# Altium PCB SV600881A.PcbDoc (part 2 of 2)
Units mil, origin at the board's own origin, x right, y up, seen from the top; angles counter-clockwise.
Board outline 3700 x 3510 mil, 4 copper layers (Top Layer, MidLayer1, MidLayer2, Bottom Layer), stack 62.2 mil thick; 110 components, 46 nets, 261 pads, 195 vias.
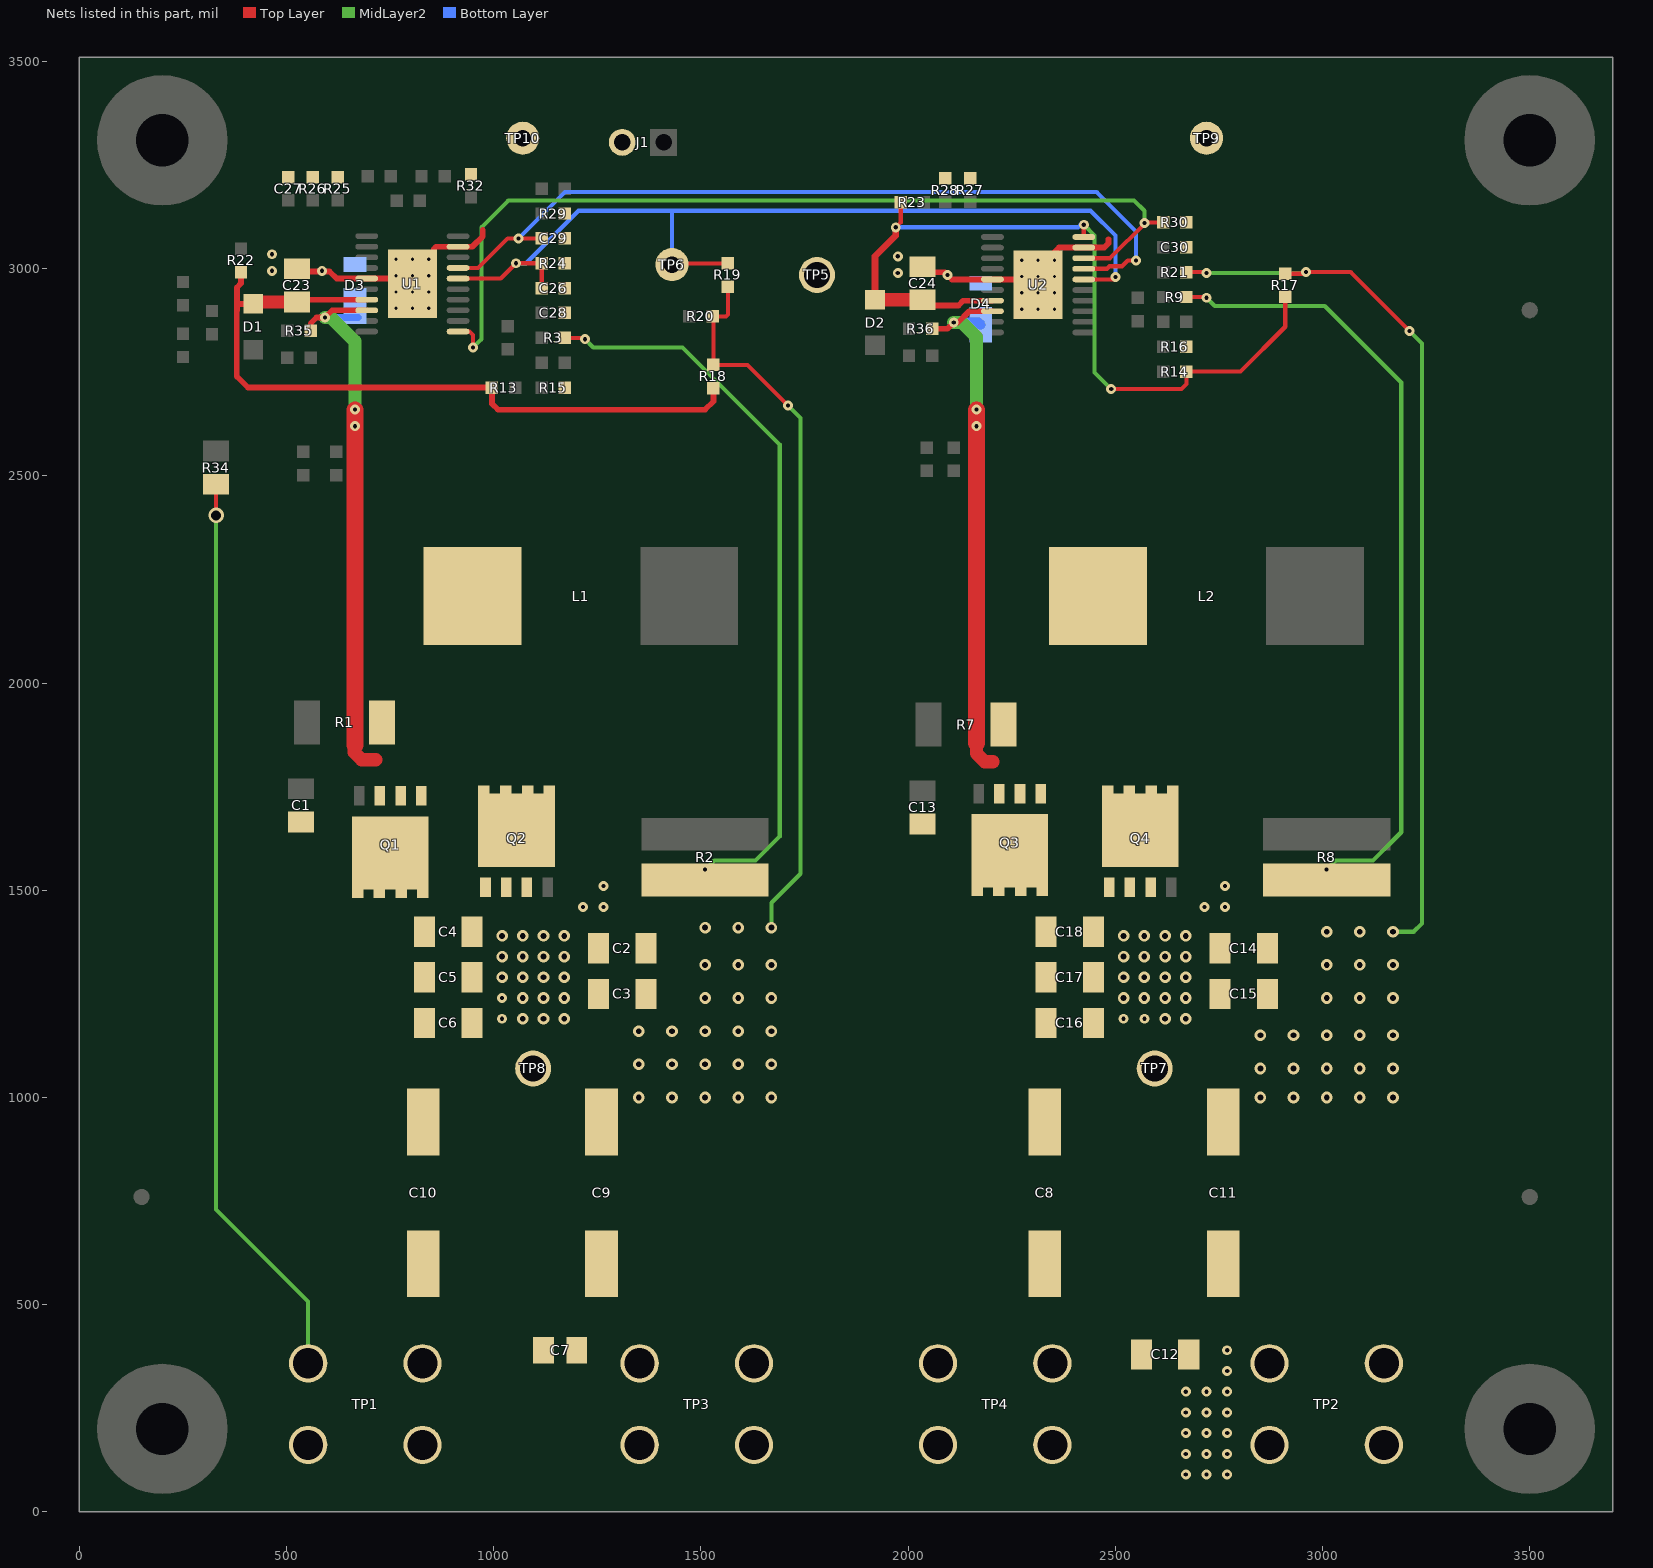
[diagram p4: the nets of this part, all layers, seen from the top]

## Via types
v1: diameter 24, hole 10, Top Layer to Bottom Layer, 84 vias
v2: diameter 28, hole 14, Top Layer to Bottom Layer, 84 vias
v3: diameter 19.68, hole 7.87, Top Layer to Bottom Layer, 24 vias
v4: diameter 38, hole 24, Top Layer to Bottom Layer, 2 vias
v5: diameter 26, hole 10, Top Layer to Bottom Layer, 1 vias

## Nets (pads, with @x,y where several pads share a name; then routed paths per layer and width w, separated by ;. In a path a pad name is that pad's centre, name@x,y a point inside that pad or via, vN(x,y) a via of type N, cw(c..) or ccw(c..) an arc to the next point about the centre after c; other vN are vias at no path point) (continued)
SGND: C2.2 C3.2 C4.2 C5.2 C6.2 C7.2 C8.2 C9.2 C10.2 C11.2 C12.2 C14.2 C15.2 C16.2 C17.2 C18.2 C23.1 C24.1 C26.2 C27.2 C28.2 C29.2 C30.2 D3.2 D4.2 J1.2 Q2.1 Q2.2 Q2.3 Q4.1 Q4.2 Q4.3 R15.1 R16.1 R24.1 R25.1 R26.1 R27.1 R28.1 R29.1 R30.1 R32.2 TP3.1 TP3.2 TP3.3 TP3.4 TP4.1 TP4.2 TP4.3 TP4.4 TP5.1 TP7.1 TP8.1 TP9.1 TP10.1 U1.9 U1.15 U1.21 U2.9 U2.15 U2.21 | length 894.8
  Top Layer w10: U1.21@800.81,2910.81 U1.21@813.6,2923.6
  Top Layer w12: U1.21@757.34,2976.4 v3(764.23,2983.29) ; v3(842.97,3022.66) 853.6,3033.29 U1.21@853.6,3043.6
  Top Layer w13.78: C23.1@543.6,2993.6 603.6,2993.6 620.81,2976.4 U1.15@693.37,2976.4 U1.21@757.34,2976.4 ; 855.6,3047.6 861.17,3053.17 U1.9@913.84,3053.17 948.17,3053.17 973.6,3078.6 973.6,3093.6 ; C24.1@2053.62,2991.5 2088.5,2991.5 v1(2095,2985) 2105.71,2974.29 U2.15@2203.39,2974.29 2267.36,2974.29 v3(2274.25,2981.18) ; U2.21@2313.62,2961.5 v3(2313.62,2981.18) 2313.62,3000.63 2364.06,3051.06 U2.9@2423.86,3051.06 2473.19,3051.06 2483.62,3061.5 2483.62,3071.5
  other v1: 1020,1190 2520,1190 2570,1190 1020,1240 1215,1460 1265,1460 2715,1460 2765,1460 1265,1510 2765,1510 1975,2990 465,2995 585,2995 1975,3030 465,3035
  other v2: 1070,1190 1120,1190 1170,1190 2620,1190 2670,1190 1070,1240 1120,1240 1170,1240 2520,1240 2570,1240 2620,1240 2670,1240 1020,1290 1070,1290 1120,1290 1170,1290 2520,1290 2570,1290 2620,1290 2670,1290 1020,1340 1070,1340 1120,1340 1170,1340 2520,1340 2570,1340 2620,1340 2670,1340 1020,1390 1070,1390 1120,1390 1170,1390 2520,1390 2570,1390 2620,1390 2670,1390
  other v3: 2274.25,2902.44 2313.62,2902.44 2352.99,2902.44 764.23,2904.55 803.6,2904.55 842.97,2904.55 2274.25,2941.81 2313.62,2941.81 2352.99,2941.81 764.23,2943.92 803.6,2943.92 842.97,2943.92 2352.99,2981.18 803.6,2983.29 842.97,2983.29 2274.25,3020.55 2313.62,3020.55 2352.99,3020.55 764.23,3022.66 803.6,3022.66
SS: C29.1 U1.7 U2.7 | length 2011.4
  Top Layer w10: U1.7@913.84,3001.99 962.3,3001.99 1033.6,3073.29 v1(1060,3073.29) C29.1@1115.6,3073.29 ; U2.7@2423.86,2999.88 2469.88,2999.88 2470,3000 2480,3000 2486,3006 2516,3006 2530,3020 v1(2550,3020)
  Bottom Layer w10: v1(1060,3073.29) 1171.71,3185 2455,3185 2550,3090 v1(2550,3020)
SW1: D3.1 L1.2 Q1.1 Q1.2 Q1.3 Q2.5 Q2.6 Q2.7 Q2.8 Q2.9 R1.1 R35.1 U1.18 | length 1435.3
  Top Layer w13.75: R35.1@558,2850 558,2868 572.2,2882.2 v1(592.52,2882.2) 609.94,2899.63 U1.18@693.37,2899.63
  Top Layer w32: 665,1850 662.96,1847.96 662.96,1832.96 680.91,1815 715,1815
  Top Layer w40: 665,1850 v1(665,2620) v1(665,2660)
  MidLayer2 w32: v1(592.52,2882.2) 607.8,2882.2 665,2825 v1(665,2660) v1(665,2620)
  Bottom Layer w16: v1(592.52,2882.2) D3.1@672.8,2882.2
SW2: D4.1 L2.2 Q3.1 Q3.2 Q3.3 Q4.5 Q4.6 Q4.7 Q4.8 Q4.9 R7.1 R36.1 U2.18 | length 1392.9
  Top Layer w13: v1(2110,2870) v1@2120,2870
  Top Layer w13.75: R36.1@2058,2855 2095,2855 v1(2110,2870) ; v1@2120,2870 2147.52,2897.52 U2.18@2203.39,2897.52
  Top Layer w32: 2165,1855 2165,1830 2185,1810 2205,1810
  Top Layer w40: 2165,1855 v1(2165,2620) v1(2165,2660)
  MidLayer2 w32: v1(2110,2870) 2130,2870 2165,2835 v1(2165,2660) v1(2165,2620)
  Bottom Layer w24: v1(2110,2870) 2169.8,2870 D4.1@2175,2864.8
SYNC: R30.2 U1.1 U2.8 | length 2262.7
  Top Layer w10: U1.1@913.84,2848.44 941.56,2848.44 950,2840 v1(950,2810) ; U2.8@2423.86,3025.47 2487.28,3025.47 2573.62,3111.81 R30.2@2615.62,3111.81
  MidLayer2 w10: v1(950,2810) 970,2830 970,3100 1035,3165 2545,3165 2570,3140 v1(2570,3110)
UVLO: C26.1 R19.1 R24.2 TP6.1 U1.6 U2.6 | length 2250.2
  Top Layer w10: U1.6@913.84,2976.4 1016.71,2976.4 v1(1053.6,3013.29) R24.2@1115.6,3013.29 C26.1@1115.6,2953.29 ; TP6.1@1430,3010 1433,3013 R19.1@1565,3013 ; U2.6@2423.86,2974.29 2494.29,2974.29 v1(2500,2980)
  Bottom Layer w10: v1@1056.89,3010 v1(1053.6,3013.29) 1078.11,3013.29 1204.83,3140 1430,3140 ; TP6.1@1430,3010 1430,3140 ; v1(2500,2980) 2500,3080 2440,3140 1430,3140
V+: C2.1 C3.1 C12.1 C14.1 C15.1 R2.1 R3.2 R8.1 R9.2 R17.2 R18.1 R19.2 R20.2 R21.2 TP2.1 TP2.2 TP2.3 TP2.4 | length 7611.7
  Top Layer w10: R3.2@1171.6,2833.29 1216.71,2833.29 v1(1220,2830) ; R20.2@1528,2890 R20.2@1530,2888 ; R19.2@1565,2957 1565,2890 1560,2885 1533,2885 R20.2@1530,2888 ; v1(1710,2670) 1612,2768 R18.1@1530,2768 R20.2@1530,2888 ; R9.2@2671.62,2931.81 2718.19,2931.81 v1(2720,2930) ; R21.2@2671.62,2991.81 2718.19,2991.81 v1(2720,2990) ; R17.2@2910,2988 2956,2988 v1(2960,2992) 3068,2992 v1(3210,2850)
  MidLayer2 w10: v1(1220,2830) 1240,2810 1455.46,2810 1690,2575.46 1690,1630 1632,1572 1532,1572 v1(1510,1550) ; v2(1670,1410) 1670,1470 1740,1540 1740,2640 v1(1710,2670) ; v1(2720,2930) 2740,2910 3005.46,2910 3190,2725.46 3190,1640 3122,1572 3032,1572 v1(3010,1550) ; v1(2720,2990) 2958,2990 v1(2960,2992) ; v2(3170,1400) 3220,1400 3240,1420 3240,2820 v1(3210,2850)
  other v1: 2670,90 2720,90 2770,90 2670,140 2720,140 2770,140 2670,190 2720,190 2770,190 2670,240 2720,240 2770,240 2670,290 2720,290 2770,290 2770,340 2770,390
  other v2: 1350,1000 1430,1000 1510,1000 1590,1000 1670,1000 2850,1000 2930,1000 3010,1000 3090,1000 3170,1000 2850,1070 2930,1070 3010,1070 3090,1070 3170,1070 1350,1080 1430,1080 1510,1080 1590,1080 1670,1080 2850,1150 2930,1150 3010,1150 3090,1150 3170,1150 1350,1160 1430,1160 1510,1160 1590,1160 1670,1160 1510,1240 1590,1240 1670,1240 3010,1240 3090,1240 3170,1240 1510,1320 1590,1320 1670,1320 3010,1320 3090,1320 3170,1320 3010,1400 3090,1400 1510,1410 1590,1410
VCC: C23.2 D1.2 R13.2 R18.2 R22.2 U1.17 | length 1824.1
  Top Layer w13.78: 380,2900 380,2740 406.71,2713.29 R13.2@995.6,2713.29 995.6,2674.4 1010,2660 1510,2660 1530,2680 R18.2@1530,2712 ; 380,2915.12 D1.2@420,2915.12 D1.2@425,2915.12 ; C23.2@525,2930 548.32,2930 C23.2@543.6,2925.29 ; C23.2@553.6,2925.22 U1.17@693.37,2925.22
  Top Layer w14: 380,2900 380,2915.12 380,2955 390,2965 R22.2@390,2992
  Top Layer w16: D1.2@425,2915.12 D1.2@429.88,2920
  Top Layer w32: D1.2@429.88,2920 C23.2@525,2920 C23.2@530,2920
VCC2: C24.2 D2.2 R14.2 R17.1 R23.2 U2.10 U2.17 | length 2044.4
  Top Layer w10: v1(1970,3100) 1982,3112 R23.2@1982,3160 ; v1@2420,3110 v1(2423.86,3106.14) U2.10@2423.86,3076.65 ; v1(2490,2710) 2660,2710 2671.62,2721.62 R14.2@2671.62,2751.81 2801.81,2751.81 2910,2860 R17.1@2910,2932
  Top Layer w13.78: C24.2@2045,2925 2058.5,2911.5 2121.5,2911.5 2133.11,2923.11 U2.17@2203.39,2923.11
  Top Layer w16: D2.2@1920,2915.12 D2.2@1920,2925.12 1920,3030 1970,3080 v1(1970,3100)
  Top Layer w32: D2.2@1929.88,2925 C24.2@2035,2925 C24.2@2045,2925
  MidLayer2 w10: v1@2420,3110 v1(2423.86,3106.14) 2450,3080 2450,2750 v1(2490,2710)
  Bottom Layer w10: v1(1970,3100) 2410,3100 v1@2420,3110
VOUT: C1.1 C4.1 C5.1 C6.1 C7.1 C8.1 C9.1 C10.1 C11.1 C13.1 C16.1 C17.1 C18.1 Q1.5 Q1.6 Q1.7 Q1.8 Q1.9 Q3.5 Q3.6 Q3.7 Q3.8 Q3.9 R34.1 TP1.1 TP1.2 TP1.3 TP1.4 | length 2213.5
  Top Layer w10: v4(330,2405) R34.1@330,2480
  MidLayer2 w10: v4(330,2405) 330,730 552,508 TP1.3@552,358.5
pads on no net: FID1.1 FID2.1 FID3.1 H3.1 H4.1 H7.1 H8.1 U2.1

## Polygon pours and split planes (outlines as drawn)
SGND on Top Layer "Top Layer-No Net 17" (solid, pour order 35): 745,3120 750,3125 855,3125 860,3120 860,2825 885,2800 910,2800 915,2795 915,2735 910,2730 705,2730 700,2735 700,2795 705,2800 720,2800 745,2825
V+ on Top Layer "Top Layer-No Net 2" (solid, pour order 53): 2820,450 3220,450 3220,1550 3210,1560 2830,1560 2820,1550
V+ on Top Layer "Top Layer-No Net 2" (solid, pour order 43): 1320,970 1330,960 1710,960 1720,970 1720,1550 1710,1560 1330,1560 1320,1550
NetL1_1 on Top Layer "Top Layer-No Net 3" (solid, pour order 46): 1720,1610 1710,1600 1330,1600 1320,1610 1320,2320 1340,2340 1700,2340 1720,2320
SW1 on Top Layer "Top Layer-No Net 4" (solid, pour order 49): 1280,1570 1270,1560 910,1560 900,1570 900,1690 890,1700 700,1700 700,2320 720,2340 1070,2340 1090,2320 1090,2010 1280,1820
SW2 on Top Layer "Top Layer-No Net 4" (solid, pour order 50): 2780,1570 2770,1560 2410,1560 2400,1570 2400,1690 2390,1700 2200,1700 2200,2320 2220,2340 2570,2340 2590,2320 2590,2010 2780,1820
NetL2_1 on Top Layer "Top Layer-No Net 3" (solid, pour order 47): 3220,1610 3210,1600 2830,1600 2820,1610 2820,2330 2840,2350 3200,2350 3220,2330
SGND on Top Layer "Top Layer-No Net 1" (solid, pour order 48): 2290,850 2300,840 2790,840 2800,850 2800,1520 2790,1530 2410,1530 2400,1520 2400,1100 2380,1080 2320,1080 2290,1050
VOUT on Top Layer "Top Layer-No Net 5" (solid, pour order 51): 2280,960 2280,1060 2310,1090 2380,1090 2380,1660 2360,1680 1790,1680 1770,1650 1770,960
VOUT on Top Layer "Top Layer-No Net 6" (solid, pour order 56): 400,50 380,70 380,305 330,380 330,950 350,970 880,970 880,940 1750,940 1770,960 2280,960 2280,840 2300,820 2790,820 2810,800 2810,490 2790,470 1160,470 1140,450 1140,70 1120,50
SGND on Top Layer "Top Layer-No Net" (solid, pour order 42): 1155,2690 1155,3155 1065,3155 983.6,3073.29 980,3070 960,3070 960,3190 950,3200 920,3200 910,3210 910,3250 900,3260 650,3260 640,3250 640,3220 630,3210 480,3210 470,3220 470,3340 480,3350 1350,3350 1370,3330 1370,2710 1350,2690
VOUT on Top Layer "Top Layer-No Net 5" (solid, pour order 52): 880,960 880,1670 870,1680 340,1680 330,1670 330,960
V+ on Top Layer "Top Layer-No Net 11" (solid, pour order 41): 2660,450 3220,450 3220,60 3210,50 2660,50 2650,60 2650,440
SGND on Top Layer "Top Layer-No Net 10" (solid, pour order 54): 1200,50 1180,70 1180,430 1200,450 2570,450 2590,430 2590,70 2570,50 1890,50 1880,60 1880,410 1870,420 1830,420 1820,410 1820,60 1810,50
SGND on Top Layer "Top Layer-No Net 1" (solid, pour order 45): 800,847.76 1290,847.76 1300,860 1300,1520 1290,1530 910,1530 900,1520 900,1115 815,1115 790,1090 790,860
SGND on Top Layer "Top Layer-No Net 9" (solid, pour order 34): 2125,2970 1955,2970 1955,3040 1965,3055 2085,3055 2100,3040 2100,3015 2125,2990
SGND on Top Layer "Top Layer-No Net 7" (solid, pour order 33): 450,3055 450,2975 610,2975 610,2995 550,3055
SGND on Top Layer "Top Layer-No Net 17" (solid, pour order 37): 2255,3130 2245,3140 2230,3140 2220,3150 2220,3190 2230,3200 2410,3200 2420,3190 2420,3150 2410,3140 2380,3140 2370,3130 2370,2825 2395,2800 2410,2800 2420,2790 2420,2730 2410,2720 2220,2720 2210,2730 2210,2790 2220,2800 2230,2800 2255,2825
SGND on Top Layer "Top Layer-No Net 8" (solid, pour order 40): 2655,2780 2655,3150 2580,3150 2485,3055 2450,3055 2470,3075 2470,3165 2425,3210 2070,3210 2070,3340 2080,3350 2850,3350 2870,3330 2870,2780
V+ on MidLayer2 "MidLayer2-No Net" (solid, pour order 59): 2660,50 3290,50 3310,70 3310,310 3450,450 3450,1430 3430,1450 2840,1450 2820,1430 2820,1160 2800,1140 1740,1140 1720,1160 1720,1430 1700,1450 1340,1450 1320,1430 1320,550 1340,530 2620,530 2640,510 2640,70
SGND on MidLayer2 "MidLayer1-No Net" (solid, pour order 60): 3650,50 1890,50 1880,60 1880,410 1870,420 1830,420 1820,410 1820,60 1810,50 50,50 49.29,3459.92 3649.29,3459.92
SW1 on Bottom Layer "Bottom Layer-No Net" (solid, pour order 61): 690,2870 585,2870 580,2875 580,2890 585,2895 690,2895
SW2 on Bottom Layer "Bottom Layer-No Net 1" (solid, pour order 62): 2195,2855 2100,2855 2095,2860 2095,2880 2100,2885 2195,2885
SGND on Bottom Layer "MidLayer1-No Net" (solid, pour order 63): 3650,50 1890,50 1880,60 1880,410 1870,420 1830,420 1820,410 1820,60 1810,50 50,50 50,3460 3650,3460
SGND on MidLayer1 "MidLayer1-No Net" (solid, pour order 57): 3650,50 1890,50 1880,60 1880,410 1870,420 1830,420 1820,410 1820,60 1810,50 50,50 50,3460 3650,3460

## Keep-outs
Keep-Out Layer:
  lines w10: -5,-5 3705,-5 3705,3515 -5,3515 -5,-5
  text ".Layer_Name" at -78,-863.49 h60

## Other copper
Top Layer:
  rectangle net NetC1_2: 485,1720 585,1980
  rectangle net NetC13_2: 1990,1715 2080,1975
  pour cut-out: 725,2832.5 725,3097.5 735,3097.5 735,2832.5
  pour cut-out: 870,2827.5 870,3092.5 880,3092.5 880,2827.5
  pour cut-out: 2239.25,2827.47 2239.25,3092.47 2249.25,3092.47 2249.25,2827.47
  pour cut-out: 2380,2827.5 2380,3092.5 2390,3092.5 2390,2827.5
  pour cut-out: 2820,1587.76 3224.68,1587.76 3224.68,1572.24 2820,1572.24
  pour cut-out: 1320,1587.76 1724.68,1587.76 1724.68,1572.24 1320,1572.24
  text ".Layer_Name" at -78,-863.49 h60
MidLayer1:
  pour cut-out: 1270,3290 1280,3275 1300,3265 1320,3265 1340,3275 1350,3290 1350,3320 1340,3335 1320,3345 1300,3345 1280,3335 1270,3320
  pour cut-out: 1030,3300 1040,3285 1060,3275 1080,3275 1100,3285 1110,3300 1110,3330 1100,3345 1080,3355 1060,3355 1040,3345 1030,3330
  pour cut-out: 2680,3300 2690,3285 2710,3275 2730,3275 2750,3285 2760,3300 2760,3330 2750,3345 2730,3355 2710,3355 2690,3345 2680,3330
  pour cut-out: 2680,3300 2690,3285 2710,3275 2730,3275 2750,3285 2760,3300 2760,3330 2750,3345 2730,3355 2710,3355 2690,3345 2680,3330
  text ".Layer_Name" at -80,-865 h60
MidLayer2:
  pour cut-out: 2680,3300 2690,3285 2710,3275 2730,3275 2750,3285 2760,3300 2760,3330 2750,3345 2730,3355 2710,3355 2690,3345 2680,3330
  pour cut-out: 1030,3300 1040,3285 1060,3275 1080,3275 1100,3285 1110,3300 1110,3330 1100,3345 1080,3355 1060,3355 1040,3345 1030,3330
  pour cut-out: 1270,3290 1280,3275 1300,3265 1333.33,3265 1350,3290 1350,3320 1340,3335 1320,3345 1300,3345 1280,3335 1270,3320
  text ".Layer_Name" at -80,-865 h60
Bottom Layer:
  pour cut-out: 1270,3290 1280,3275 1300,3265 1320,3265 1340,3275 1350,3290 1350,3320 1340,3335 1320,3345 1300,3345 1280,3335 1270,3320
  pour cut-out: 1090,3265 1050,3265 1020,3295 1020,3335 1050,3365 1090,3365 1120,3335 1120,3295
  pour cut-out: 2745,3265 2700,3265 2670,3295 2670,3340 2695,3365 2740,3365 2770,3335 2770,3295
  text ".Layer_Name" at -78,-863.49 h60

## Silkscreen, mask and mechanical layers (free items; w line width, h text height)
Top Overlay:
  lines w7: 655,2785 655,2795 625,2825 ; 2170,2780 2160,2790 2125,2790 2110,2805 ; 625,2825 625,2810 640,2825 625,2825 ; 2110,2805 2110,2790 2125,2805 2110,2805
  text "EXT" at 1250,3375 h44
  text "SYNC" at 1420,3375 h44
  text "LM5122EVM-2PH" at 175,1380 h78.74 r90
  text "HOT SURFACE" at 3555,875 h78.74 r90
  text "HOT SURFACE" at 2060,735 h78.74 r90
  text "28VDC" at 130,610 h70
  text "9-20VDC" at 3060,600 h70
  text "7A" at 205,500 h70
  text "GND" at 1445,495 h60
  text "GND" at 1985,495 h60
  text "30A MAX" at 3170,490 h60
  text "VOUT" at 450,475 h60
  text "VIN" at 2905,465 h60
  text "MAX" at 185,410 h60
  text ".Layer_Name" at -78,-863.49 h60
Bottom Overlay:
  region: 85,2370 85,2070 185,2070 185,2370
  text "-" at 84.5,2005 h60 r270
  text "A" at 105,1970 h60 r270
  text ".PRJ_Number" at 105,1435 h60 r270
  text ".Layer_Name" at -78,-863.49 h60
Top Paste:
  text ".Layer_Name" at -78,-863.49 h60
Bottom Paste:
  text ".Layer_Name" at -78,-863.49 h60
Top Solder:
  circle w45: c1235,1625 r20
  circle w45: c2735,1635 r20
  text ".Layer_Name" at -78,-863.49 h60
  text ".Layer_Name" at -78,-863.49 h60
Bottom Solder:
  text ".Layer_Name" at -78,-863.49 h60
Drill Guide:
  text ".Layer_Name" at -78,-863.49 h60
M1 Board Outline:
  the board outline again, w10
  text ".Layer_Name" at -78,-863.49 h60
M2 Board Dimensions:
  rectangle: -655.5,-290.5 -530.5,-165.5
  rectangle: -530.5,-415.5 -155.5,-290.5
  lines w7: -655.5,-290.5 344.5,-290.5 ; -530.5,-415.5 -530.5,-165.5 ; -405.5,-415.5 -405.5,-165.5 ; -155.5,-415.5 -155.5,-165.5 ; 94.5,-415.5 94.5,-165.5 ; -655.5,-415.5 344.5,-415.5 344.5,-165.5 -655.5,-165.5 -655.5,-415.5
  lines w10: -655.5,-480.5 -655.5,-460.5 ; -595.5,-490.5 -655.5,-470.5 ; -595.5,-450.5 -655.5,-470.5 ; -431.42,-470.5 -655.5,-470.5 ; 120.42,-470.5 344.5,-470.5 ; 284.5,-490.5 344.5,-470.5 ; 284.5,-450.5 344.5,-470.5 ; 344.5,-480.5 344.5,-460.5
  text "1000 (mil)" at -421.42,-506.49 h60
  text ".Layer_Name" at -78,-863.49 h60
M3 3D STEP Top:
  text ".Layer_Name" at -78,-863.49 h60
M4 3D STEP Bottom:
  text ".Layer_Name" at -78,-863.49 h60
M5 Assembly Top:
  lines w7: 4524,55.5 5649,55.5 ; 4524,178 5646.5,178 ; 4839,-64.5 4839,298 ; 5224,-64.5 4524,-64.5 ; 5224,298 4524,298 ; 4524,-64.5 5649,-64.5 5649,298 4524,298 ; 4524,-64.5 4524,298
  lines w10: -947,-930.17 5653,-930.17 ; -947,-726.83 5655,-726.83 ; -947,-523.5 -947,-1133.5 3058,-1133.5 5655,-1133.5 5655,-523.5 -946.5,-523.5 -946.5,-1133.5 629,-1133.5 ; 1518,-1133.5 1518,-523.5 ; 2785,-726.83 2785,-523.5 ; 3625,-726.83 3625,-523.5 ; 4247,-1140 4247,-937.17
  text "TABLE 1" at 4911.5,333 h40
  text "Variant" at 4549,223 h40
  text "Label text" at 4984,223 h40
  text "001" at 4616.5,103 h40
  text "LM5122EVM-2PH" at 4894,100.5 h40
  text "002" at 4616.5,-22 h40
  text "N/A" at 4889,-24.5 h40
  text "COMPONENTS MARKED 'DNP' SHOULD NOT BE POPULATED, AND MAY NOT BE IN BILL OF MATERIALS" at 498.5,-318.5 h60
  text "ASSEMBLY VARIANT:" at 498,-434 h60
  text ".VariantName" at 1534,-434 h60
  text "PCB VIEWED FROM TOP SIDE" at -883.5,-655.67 h60
  text "BOARD #:" at 1593,-655.67 h60
  text ".PRJ_Number" at 2138.5,-655.67 h60
  text "REV:" at 2983,-655.67 h60
  text ".PCB_Rev" at 3274.5,-655.67 h60
  text "SVN REV:" at 3821,-655.67 h60
  text ".VersionControl_RevNumber" at 4327,-655.67 h60
  text "IGNORE ->" at -883.5,-858.49 h60
  text ".Layer_Name" at -80,-860 h60
  text "PLOT NAME =" at -883.5,-1064.34 h60
  text ".plot_File_Name" at -78,-1064.34 h60
  text "GENERATED    :" at 1595,-1064.34 h60
  text ".Print_Date" at 2464.5,-1064.34 h60
  text ".Print_Time" at 3193.5,-1064.34 h60
  text "TEXAS INSTRUMENTS" at 4458,-1064.34 h60
M6 Assembly Bottom:
  lines w10: -947.5,-727.33 5654.5,-727.33 ; -945.5,-930.67 5654.5,-930.67 ; 460.5,-1140.5 460.5,-937.67 ; 1082.5,-727.33 1082.5,-524 ; 1922.5,-727.33 1922.5,-524 ; 3189.5,-1134 3189.5,-524 ; 4078.5,-1134 5654,-1134 5654,-524 -947.5,-524 -947.5,-1134 1649.5,-1134 5654.5,-1134 5654.5,-524
  text "COMPONENTS MARKED 'DNP' SHOULD NOT BE POPULATED, AND MAY NOT BE IN BILL OF MATERIALS" at 5447,-318 h60
  text ".VariantName" at 4403,-434 h60
  text "ASSEMBLY VARIANT:" at 5442,-434 h60
  text ".VersionControl_RevNumber" at 380.5,-656.17 h60
  text "SVN REV:" at 886.5,-656.17 h60
  text ".PCB_Rev" at 1433,-656.17 h60
  text "REV:" at 1724.5,-656.17 h60
  text ".PRJ_Number" at 2569,-656.17 h60
  text "BOARD #:" at 3114.5,-656.17 h60
  text "PCB VIEWED FROM BOTTOM SIDE" at 5591,-656.17 h60
  text "IGNORE ->" at 1892.85,-858.49 h60
  text ".Layer_Name" at -80,-860 h60
  text "TEXAS INSTRUMENTS" at 249.5,-1064.84 h60
  text ".Print_Time" at 1514,-1064.84 h60
  text ".Print_Date" at 2243,-1064.84 h60
  text "GENERATED    :" at 3112.5,-1064.84 h60
  text ".plot_File_Name" at 4785.5,-1064.84 h60
  text "PLOT NAME =" at 5591,-1064.84 h60
M9 Title Sheet:
  lines w10: -1146.5,1041.5 -946.5,1041.5 ; -1146.5,3416.5 -946.5,3416.5 ; -1146.5,5791.5 -946.5,5791.5 ; 1353.5,-1333.5 1353.5,-1133.5 ; 1353.5,7966.5 1353.5,8166.5 ; 3853.5,-1333.5 3853.5,-1133.5 ; 3853.5,7966.5 3853.5,8166.5 ; 5666,-1133.5 5666,-523.5 10648.5,-523.5 ; 6353.5,-1333.5 6353.5,-1133.5 ; 6353.5,7966.5 6353.5,8166.5 ; 8853.5,-1333.5 8853.5,-1133.5 ; 8853.5,7966.5 8853.5,8166.5 ; 10648.5,-1133.5 10648.5,-523.5 ; 10648.5,-823.5 13648.5,-823.5 ; 10648.5,-223.5 13648.5,-223.5 ; 10649.5,370.5 13649.5,370.5 ; 11353.5,-1333.5 11353.5,-1133.5 ; 11353.5,7966.5 11353.5,8166.5 ; 12153.5,-1123.5 12153.5,-523.5 ; 13648.5,-523.5 10648.5,-523.5 ; 13648.5,76.5 10648.5,76.5 ; 13653.5,66.5 13653.5,-1133.5 ; 13653.5,871 10649.5,871 10648.5,871 10648.5,370.5 10648.5,76.5 ; 13653.5,1041.5 13853.5,1041.5 ; 13653.5,3416.5 13853.5,3416.5 ; 13653.5,5791.5 13853.5,5791.5 ; 10648.5,-523.5 10648.5,76.5 ; 13653.5,-1133.5 13653.5,7966.5 -946.5,7966.5 -946.5,-1133.5 13653.5,-1133.5 ; -1146.5,-1333.5 -1146.5,8166.5 13853.5,8166.5 13853.5,-1333.5 -1146.5,-1333.5
  text "1" at 84.84,8036.5 h70
  text "2" at 2580.5,8036.5 h70
  text "3" at 5069.84,8036.5 h70
  text "4" at 7576.51,8036.5 h70
  text "5" at 10075.5,8036.5 h70
  text "6" at 12580.5,8036.5 h70
  text "A" at -1071.5,6893.5 h70
  text "A" at 13728.5,6893.5 h70
  text "B" at -1071.5,4513.5 h70
  text "B" at 13728.5,4513.5 h70
  text "C" at -1071.5,2138.5 h70
  text "C" at 13728.5,2138.5 h70
  text "PROJECT TITLE:" at 10688.5,277.5 h45
  text ".PRJ_Title" at 10738.5,144.17 h70
  text "DESIGNED FOR:" at 10688.5,-23.5 h45
  text ".PRJ_Customer" at 10738.5,-163.5 h70
  text "D" at -1071.5,-231.5 h70
  text "D" at 13728.5,-231.5 h70
  text "FILE NAME:" at 10688.5,-323.5 h45
  text ".PCB_File_Name_No_Path" at 10738.5,-443.5 h70
  text "ENGINEER:" at 10688.5,-613.5 h45
  text "LAYOUT BY:" at 12193.5,-613.5 h45
  text ".PRJ_Engineer" at 10738.5,-768.49 h70
  text ".PCB_Layout" at 12244,-768.49 h70
  text "ALTIUM DESIGNER VERSION:" at 12193.5,-923.5 h45
  text ".print_Scale" at 10738.5,-1056.83 h70
  text ".Application_BuildNumber" at 12244,-1056.83 h70
  text "1" at 84.84,-1263.5 h70
  text "2" at 2580.5,-1263.5 h70
  text "3" at 5069.84,-1263.5 h70
  text "4" at 7576.51,-1263.5 h70
  text "5" at 10075.5,-1263.5 h70
  text "6" at 12580.5,-1263.5 h70
M10 Fab Notes:
  drawing of 203 lines, arcs and shapes, not listed
  text "DESIGN INFORMATION" at 11721.02,6810 h60
  text "(REFER ALSO ARRAY/PANEL PROFILING INFORMATION)" at 11359.46,6648.29 h60
  text "BOARD SIZE" at 10673.46,6644 h60
  text "3700MIL" at 11135.78,6516.18 h60
  text "X" at 11641.46,6516.18 h60
  text "3150MIL" at 11872.78,6516.18 h60
  text "Number of Layers :" at 11076.46,6319 h60
  text "4" at 12171.27,6309 h60
  text "MIN. TRACK WIDTH:" at 11076.46,6180 h60
  text "8" at 12172.7,6180 h60
  text "MIL" at 12327.46,6180 h60
  text "MIN. CLEARANCE:" at 11076.46,6048 h60
  text "8" at 12172.7,6048 h60
  text "MIL" at 12327.46,6048 h60
  text "MIN. VIA PAD SIZE:" at 11076.46,5916 h60
  text "20" at 12142.71,5916 h60
  text "MIL" at 12327.46,5916 h60
  text "0.05mm (2MIL)" at 11771.46,5774.29 h60
  text "MINIMUM ANNULAR RING" at 10747.23,5770 h60
  text "EXTERNAL" at 12479.46,5770 h60
  text "PER" at 10947.23,5652 h60
  text "IPC-D-275 CLASS 2 LEVEL C" at 11167.23,5652 h60
  text "MIL, HOLES" at 12655.46,5539.71 h60
  text "+/-" at 12263,5539 h60
  text "+/-" at 13117,5539 h60
  text "REGISTRATION TOLERANCES:" at 10747.23,5534 h60
  text "METAL" at 11947,5534 h60
  text "5" at 12523.2,5534 h60
  text "3" at 13356.2,5534 h60
  text "MIL" at 13472.46,5534 h60
  text "MATERIAL:" at 10672.46,5324.54 h60
  text "FR-4 High Tg" at 11658.9,5184.21 h60
  text "FR-4" at 11133.46,5175.64 h60
  text "X" at 11505.46,5175.64 h60
  text "OTHER" at 12581.46,5175.64 h60
  text "62 MIL (1.6mm) +/-10%" at 11413.56,5012.92 h60
  text "THICKNESS:" at 10747.23,5008.64 h60
  text "X" at 11285.4,5008.64 h60
  text "OTHER" at 12698.46,5008.64 h60
  text "TOLERANCE:" at 10747.23,4850.64 h60
  text "X" at 11586.53,4850.64 h60
  text "ANSI IPC-6012 TYPE 3 CLASS 2" at 11773.48,4850.64 h60
  text "OTHER +/-" at 11773.46,4694.64 h60
  text "BOW & TWIST:" at 10747.23,4537.64 h60
  text "X" at 11586.53,4537.64 h60
  text "ANSI IPC-6012 TYPE 3 CLASS 2" at 11773.48,4537.64 h60
  text "OTHER +/-" at 11773.46,4379.13 h60
  text "COPPER THICKNESS (FINISHED):" at 10672.46,4243.64 h60
  text "1.4MIL (1oz)" at 11552.46,4090.92 h60
  text "2MIL (1.4oz)" at 12319.46,4090.92 h60
  text "2.8MIL (2oz)" at 13046.46,4090.92 h60
  text "X" at 12920,4090 h60
  text "OUTER:" at 11029.46,4086.64 h60
  text "1.4MIL (1oz)" at 11902.46,3933.92 h60
  text "2.8MIL (2oz)" at 12746.46,3933.92 h60
  text "INNER SIGNAL:" at 11029.46,3929.64 h60
  text "X" at 12620,3930 h60
  text "DRILLING:" at 10672.46,3790.64 h60
  text "REFERENCE:" at 10747.23,3673.64 h60
  text "AS SHOWN" at 11582.46,3673.64 h60
  text "X" at 12296.46,3673.64 h60
  text "NC_DRILL FILES" at 12433.46,3673.64 h60
  text "PTH MIN COPPER THICKNESS:" at 10747.23,3515.64 h60
  text "X" at 12097.46,3515.64 h60
  text "1MIL" at 12234.46,3515.64 h60
  text "OTHER" at 12731.46,3515.64 h60
  text "BOARD FINISH:" at 10672.46,3356.64 h60
  text "SILKSCREEN:" at 10827.68,3238.64 h60
  text "X" at 11776.46,3238.64 h60
  text "TOP" at 11902.46,3238.64 h60
  text "X" at 12286.46,3238.64 h60
  text "BOTTOM" at 12413.46,3238.64 h60
  text "SILKSCREEN COLOR:" at 10827.68,3071.64 h60
  text "X" at 11775.42,3071.64 h60
  text "WHITE" at 11902.46,3071.64 h60
  text "OTHER" at 12413.46,3071.64 h60
  text "SOLDER RESIST COLOR:" at 10827.68,2901.64 h60
  text "X" at 11395.42,2742.44 h60
  text "GREEN" at 11522.46,2742.44 h60
  text "BLUE" at 12113.46,2742.44 h60
  text "OTHER" at 12651.46,2742.44 h60
  text "IMMERSION GOLD (ENIG)" at 11733.46,2553.92 h60
  text "SURFACE FINISH:" at 10672.46,2549.64 h60
  text "X" at 11546.51,2549.64 h60
  text "Pb-FREE HASL" at 12965.75,2549.64 h60
  text "OTHER" at 11733.46,2392.64 h60
  text "ARRAY/PANEL:" at 10672.46,2213.64 h60
  text "CUT AND TRIM PER MECH LAYER 1" at 11733.46,2209.35 h60
  text "X" at 11550,2060 h60
  text "N.C. ROUTE" at 11733.46,2057.64 h60
  text "V. SCORE" at 12599.46,2057.64 h60
  text "CERTIFICATION:" at 10672.46,1920.64 h60
  text "MATERIALS AND WORKMANSHIP FOR ALL PCBS" at 11397.46,1920.64 h60
  text "TO MEET OR EXCEED THE REQUIREMENTS OF:" at 11397.46,1822.64 h60
  text "X" at 11023.96,1686.13 h60
  text "ANSI IPC-A-600F CLASS ->" at 11162.96,1686.13 h60
  text "X" at 12802.02,1686.13 h60
  text "2" at 12920.96,1686.14 h60
  text "1" at 12605.96,1684.64 h60
  text "3" at 13274.96,1684.64 h60
  text "X" at 11026.02,1526.64 h60
  text "UL 94V-0" at 11162.96,1526.64 h60
  text "X" at 11838.02,1526.64 h60
  text "RoHS" at 11974.96,1526.64 h60
  text "OTHER" at 12619.36,1526.64 h60
  text "PER ORDER" at 13016.42,1526.64 h60
  text "ADDITIONAL REQUIREMENTS:" at 10672.46,1385.64 h60
  text "MICROSECTION:" at 10747.23,1270.64 h60
  text "YES" at 11652.96,1270.64 h60
  text "X" at 12380,1115 h60
  text "REQUIRED" at 12514.46,1114.49 h60
  text "BARE BOARD ELEC. TEST:" at 10747.23,1111.64 h60
  text "NONE" at 12052.96,1111.64 h60
  text "PER ORDER" at 13106.46,1111.64 h60
  text "MANUFACTURER'S ID/LOGO:" at 10747.23,954.64 h60
  text "RAIL" at 12212.96,950.35 h60
  text "X" at 12587.46,950.35 h60
  text "METAL" at 12704.77,950.35 h60
  text "SILK" at 13216.46,950.35 h60
  text ".Layer_Name" at -78,-863.49 h60
M11 Gerber Information:
  lines w10: -947,-930.17 5653,-930.17 ; -947,-726.83 5655,-726.83 ; -947,-523.5 -947,-1133.5 3058,-1133.5 5655,-1133.5 5655,-523.5 -946.5,-523.5 -946.5,-1133.5 629,-1133.5 ; 1518,-1133.5 1518,-523.5 ; 2785,-726.83 2785,-523.5 ; 3625,-726.83 3625,-523.5 ; 4247,-1140 4247,-937.17
  text "ALL ARTWORK VIEWED FROM TOP SIDE" at -883.5,-655.67 h60
  text "BOARD #:" at 1593,-655.67 h60
  text ".PRJ_Number" at 2138.5,-655.67 h60
  text "REV:" at 2983,-655.67 h60
  text ".PCB_Rev" at 3274.5,-655.67 h60
  text "SVN REV:" at 3821,-655.67 h60
  text ".VersionControl_RevNumber" at 4327,-655.67 h60
  text "LAYER NAME =" at -883.5,-858.49 h60
  text "PLOT NAME =" at -883.5,-1064.34 h60
  text ".plot_File_Name" at -78,-1064.34 h60
  text "GENERATED    :" at 1595,-1064.34 h60
  text ".Print_Date" at 2464.5,-1064.34 h60
  text ".Print_Time" at 3193.5,-1064.34 h60
  text "TEXAS INSTRUMENTS" at 4458,-1064.34 h60
M12 Stackup:
  lines w5: 10700,7692.5 13570,7692.5 ; 10700,7791.8 13570,7791.8 ; 10640,6972 ccw(c10672,6972) 10672,6940 13598,6940 ccw(c13598,6972) 13630,6972 13630,7908 ccw(c13598,7908) 13598,7940 10672,7940 ccw(c10672,7908) 10640,7908 10640,6972
  text "Layer Stack Up Detail for: 551xxxxxx.PcbDoc" at 10700,7822.8 h57
  text "Layer" at 10700,7754.8 h23
  text "Gerber" at 11316.16,7754.8 h23
  text "Copper" at 11625.75,7754.8 h23
  text "Dielectric" at 11972.89,7754.8 h23
  text "Dielectric" at 12336.13,7754.8 h23
  text "Dielectric" at 12792.34,7754.8 h23
  text "Dielectric" at 13155.58,7754.8 h23
  text "Name" at 10700,7708.8 h23
  text "Document" at 11316.16,7708.8 h23
  text "Thickness" at 11625.75,7708.8 h23
  text "Height" at 11972.89,7708.8 h23
  text "Material" at 12336.13,7708.8 h23
  text "Constant" at 12792.34,7708.8 h23
  text "Type" at 13155.58,7708.8 h23
  text "Top Solder Mask" at 10700,7637.92 h32
  text "(.GTS)" at 11316.16,7637.92 h32
  text "0.4mil" at 11972.89,7637.92 h32
  text "Solder Resist" at 12336.13,7637.92 h32
  text "3.50" at 12792.34,7637.92 h32
  text "Top Layer" at 10700,7533.75 h32
  text "(.GTL)" at 11316.16,7533.75 h32
  text "2.8mil" at 11625.75,7533.75 h32
  text "17mil" at 11972.89,7481.67 h32
  text "FR-4" at 12336.13,7481.67 h32
  text "4.80" at 12792.34,7481.67 h32
  text "Core" at 13155.58,7481.67 h32
  text "MidLayer1" at 10700,7429.58 h32
  text "(.G1)" at 11316.16,7429.58 h32
  text "2.8mil" at 11625.75,7429.58 h32
  text "17mil" at 11972.89,7377.5 h32
  text "FR-4" at 12336.13,7377.5 h32
  text "4.80" at 12792.34,7377.5 h32
  text "PrePreg" at 13155.58,7377.5 h32
  text "MidLayer2" at 10700,7325.42 h32
  text "(.G2)" at 11316.16,7325.42 h32
  text "2.8mil" at 11625.75,7325.42 h32
  text "17mil" at 11972.89,7273.33 h32
  text "FR-4" at 12336.13,7273.33 h32
  text "4.80" at 12792.34,7273.33 h32
  text "Core" at 13155.58,7273.33 h32
  text "Bottom Layer" at 10700,7221.25 h32
  text "(.GBL)" at 11316.16,7221.25 h32
  text "2.8mil" at 11625.75,7221.25 h32
  text "Bottom Solder Mask" at 10700,7117.08 h32
  text "(.GBS)" at 11316.16,7117.08 h32
  text "0.4mil" at 11972.89,7117.08 h32
  text "Solder Resist" at 12336.13,7117.08 h32
  text "3.50" at 12792.34,7117.08 h32
  text ".Layer_Name" at -78,-863.49 h60
M13 Component Bodies Top:
  text ".Layer_Name" at -78,-863.49 h60
M14 Component Bodies Bottom:
  text ".Layer_Name" at -78,-863.49 h60
M15 Courtyards Top:
  text ".Layer_Name" at -78,-863.49 h60
M16 Courtyards Bottom:
  text ".Layer_Name" at -78,-863.49 h60
Drill Drawing:
  text ".legend" at 4576.5,1257.5 h60
  text "Drill Table" at 4601.5,1072.5 h60
  text ".Layer_Name" at -78,-863.49 h60

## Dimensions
0,0 to 3700,0 on M2 Board Dimensions
0,0 to 0,3510 on M2 Board Dimensions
